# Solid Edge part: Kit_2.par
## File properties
Username: psaghy
Dokumentum tartalom típus: 0
Author: psaghy
Last saved by: psaghy
Revision: 79
Sűrűség: 0,000 kg/m^3
Pontosság: 0,990
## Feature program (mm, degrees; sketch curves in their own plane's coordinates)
base feature "unnamed BaseFeature 1"
sketch for "Furat_1" plane through (0, -3.875, 7) normal (0, 0, 1) x-axis (0, 1, 0)
  hole centre (-0.625, 0) bore radius 2.067
hole "Furat_1" nominal diameter 5 finite  ThreadDepth = 4.5 mm
chamfer "Letörés_2" setback 0.5
sketch for "Kihúzás_1" #1 plane through (0, 12.5, 0) normal (0, 1, 0) x-axis (0, 0, 1)
  line (4.4721, 4) -> (-4.4721, 4)
sketch for "Kihúzás_1" #2 plane through (0, 12.5, 0) normal (0, 1, 0) x-axis (0, 0, 1)
  arc centre (0, 0) radius 6 from (4.4721, -4) to (-4.4721, -4) cw
  line (4.4721, -4) -> (-4.4721, -4)
extrude "Kihúzás_1" add finite 8.92 along -normal
thread "unnamed Thread 1"
chamfer "Letörés_3" setback 1
sketch for "Kivágás_1" #1 plane through (0, 12.5, 0) normal (0, 1, 0) x-axis (0, 0, 1)
  line (4.4721, 4) -> (-4.4721, 4)
sketch for "Kivágás_1" #2 plane through (0, 12.5, 0) normal (0, 1, 0) x-axis (0, 0, 1)
  line (4.4721, -4) -> (-4.4721, -4)
  arc centre (0, 0) radius 6 from (4.4721, -4) to (-4.4721, -4) cw
extrude "Kivágás_1" cut finite 8.92 along -normal
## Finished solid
Body 1: solid body, 30 faces, 69 edges, 40 vertices.
  Faces by surface: plane 13, cylinder 10, cone 7
  Edges by curve: line 32, circle 29, intersection 4, spline 4
Bounding box of the edges (mm): 16.000 x 22.250 x 15.000, from (-8, -9.75, -8) to (8, 12.5, 7).
Cylindrical faces by radius (mm): R2 x1, R2.067 x1, R4.6 x1, R5 x2, R6 x4, R8 x1
Conical faces (half-angle, radius in mm at the cone's reference point): 45 deg R2.067 x1, 45 deg R2.1 x2, 45 deg R6 x2, 60 deg R5.5 x2
Planar faces by outward normal: +x 1, +y 7, +z 2, -x 1, -y 2
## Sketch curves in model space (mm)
arc centre (0, 12.5, 0) radius 6 from (4, 12.5, -4.4721) through (5.9975, 12.5, 0.174) to (4, 12.5, 4.4721)
line (4, 12.5, 4.4721) -> (4, 12.5, -4.4721)
arc centre (0, 12.5, 0) radius 6 from (-4, 12.5, 4.4721) through (-5.9975, 12.5, -0.174) to (-4, 12.5, -4.4721)
line (-4, 12.5, 4.4721) -> (-4, 12.5, -4.4721)
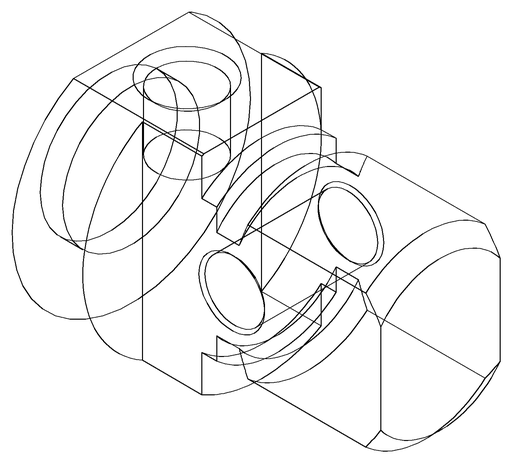
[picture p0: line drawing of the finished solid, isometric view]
